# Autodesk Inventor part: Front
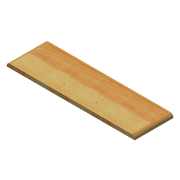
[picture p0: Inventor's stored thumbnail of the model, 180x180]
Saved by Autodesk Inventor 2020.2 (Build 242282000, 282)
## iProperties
Created: 2005-10
Part Number: Front
Document SubType Name: Modeling
Designer: F.Stasiak
Density: 1 g/cm^3
Material: Ogólny
Appearance: Drewno (sosna)
Manager: www.cadconsulting.pl
Company: Fabian Stasiak CAD Consulting
Author: F.Stasiak
Subject: Zbiór ćwiczeń. Autodesk Inventor 2020. Kurs podstawowy
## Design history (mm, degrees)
sketch "Szkic1"
  geometry: L1 (199.165, -57.385)-(-198.835, -57.385); L2 (-198.835, -57.385)-(-198.835, 62.615); L3 (-198.835, 62.615)-(199.165, 62.615); L4 (199.165, 62.615)-(199.165, -57.385)
  constraints: 8 end point, 2 parallel, 1 horizontal, 1 perpendicular
  dimensions: "d0" = 398 distance of L1.start L1.end; "d1" = 120 distance of L3.end L1.start
extrude "Wyciągnięcie proste1" new body sketch "Szkic1" distance "d2" = 12; taper "d3" = 0 deg
fillet "Zaokrąglenie1" dims "d4" = 10
sketch "Szkic2"
  geometry: L1 (-199.165, -57.385)-(198.835, -57.385) reference; L2 (198.835, -57.385)-(198.835, 62.615) reference; L3 (198.835, 62.615)-(-199.165, 62.615) reference; L4 (-199.165, 62.615)-(-199.165, -57.385) reference; L5 (-0.165, -57.385)-(-0.165, 62.615); L6 (49.835, -27.385)-(-50.165, -27.385); 3 further points
  constraints: 4 end point, 3 midpoint, 2 coincident, 1 perpendicular, 1 point on line
  dimensions: "d5" = 30 distance between parallel lines of L1 L6; "d6" = 100 distance of L6.start L6.end
hole "Otwór1" sketch "Szkic2" at (49.835, -27.385), (-50.165, -27.385) diameter "d7" = 3.5; stored, may be unused: countersink angle "d11" = 90 deg, drill point angle "d13" = 118 deg; dims "d8" = 6, "d9" = 4, "d10" = 2, "d12" = 8
node "Bryła1"
node "Korpusy bryłowe"
node "Korpusy powierzchniowe"
node "Pętla rzutowana1"
